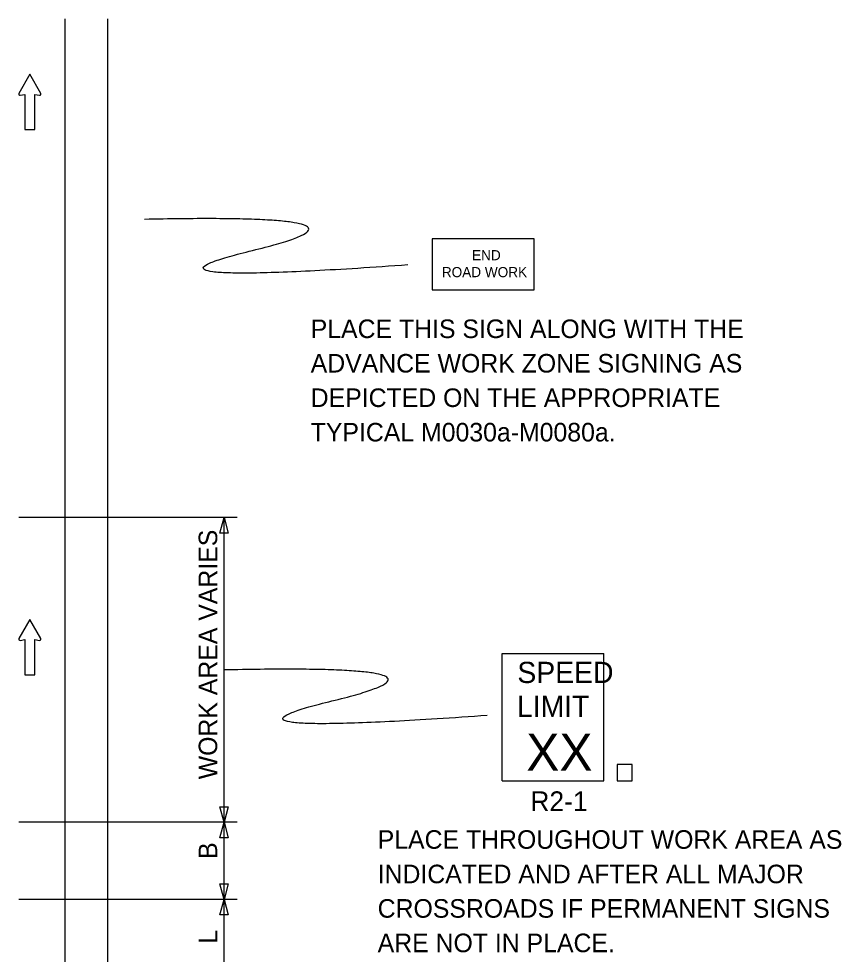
# Model space of a CAD drawing. Extents: x 16735 to 19504, y 6970 to 8243.
# Drawn here: x 18071.7 to 18381.9, y 7838.5 to 8191.4 of the extents above; entities that cross this region are included whole.
import ezdxf

# ---------------------------------------------------------------- set-up
doc = ezdxf.new("R2010")
doc.units = 0
for name, color, linetype in [('MT_SCRATCH_LEVEL_E', 7, 'Continuous'), ('PAVT_EDGE_EX', 7, 'Continuous'), ('TRAFFIC_SIGNS_PR', 7, 'Continuous'), ('TYPICAL_TEXT_DIMEN_PR', 7, 'Continuous')]:
    doc.layers.add(name, color=color, linetype=linetype)

msp = doc.modelspace()

# ---------------------------------------------------------------- linework, layer by layer
at = {"layer": 'MT_SCRATCH_LEVEL_E'}
for p, q in [((18075.82, 8170.46), (18071.71, 8163.22)), ((18075.82, 8170.46), (18071.71, 8163.22)), ((18079.97, 8163.22), (18075.82, 8170.46)), ((18079.97, 8163.22), (18075.82, 8170.46)), ((18072.19, 8162.54), (18073.97, 8162.86)), ((18072.19, 8162.54), (18073.97, 8162.86)), ((18073.97, 8162.86), (18073.97, 8149.6)), ((18073.97, 8162.86), (18073.97, 8149.6)), ((18077.71, 8149.6), (18077.71, 8162.86)), ((18077.71, 8162.86), (18079.49, 8162.54)), ((18077.71, 8149.6), (18077.71, 8162.86)), ((18077.71, 8162.86), (18079.49, 8162.54)), ((18073.97, 8149.6), (18077.71, 8149.6)), ((18073.97, 8149.6), (18077.71, 8149.6)), ((18075.82, 7964.84), (18071.71, 7957.6)), ((18075.82, 7964.84), (18071.71, 7957.6)), ((18079.97, 7957.6), (18075.82, 7964.84)), ((18079.97, 7957.6), (18075.82, 7964.84)), ((18072.19, 7956.91), (18073.97, 7957.23)), ((18072.19, 7956.91), (18073.97, 7957.23)), ((18073.97, 7957.23), (18073.97, 7943.97)), ((18073.97, 7957.23), (18073.97, 7943.97)), ((18077.71, 7943.97), (18077.71, 7957.23)), ((18077.71, 7957.23), (18079.49, 7956.91)), ((18077.71, 7943.97), (18077.71, 7957.23)), ((18077.71, 7957.23), (18079.49, 7956.91)), ((18073.97, 7943.97), (18077.71, 7943.97)), ((18073.97, 7943.97), (18077.71, 7943.97))]:
    msp.add_line(p, q, dxfattribs=at)
for centre, start, end in [((18072.12, 8163), 150.4248, 279.9638), ((18072.12, 8163), 150.4248, 279.9638), ((18079.56, 8163), 260.0362, 29.7731), ((18079.56, 8163), 260.0362, 29.7731), ((18072.12, 7957.37), 150.4248, 279.9638), ((18072.12, 7957.37), 150.4248, 279.9638), ((18079.56, 7957.37), 260.0362, 29.7731), ((18079.56, 7957.37), 260.0362, 29.7731)]:
    msp.add_arc(centre, 0.463, start, end, dxfattribs=at)
at = {"layer": 'PAVT_EDGE_EX'}
for p, q in [((18089.08, 8191.4), (18089.08, 7362.22)), ((18105.08, 8191.4), (18105.08, 7362.22))]:
    msp.add_line(p, q, dxfattribs=at)
at = {"layer": 'TRAFFIC_SIGNS_PR'}
for p, q in [((18253.94, 7951.98), (18292.34, 7951.98)), ((18253.94, 7903.98), (18253.94, 7951.98)), ((18292.34, 7903.98), (18292.34, 7951.98)), ((18253.94, 7903.98), (18292.34, 7903.98))]:
    msp.add_line(p, q, dxfattribs=at)
for points in [[(18227.62, 8089.16), (18266.02, 8089.16), (18266.02, 8108.36), (18227.62, 8108.36)], [(18297.36, 7903.98), (18302.95, 7903.98), (18302.95, 7910.15), (18297.36, 7910.15)]]:
    msp.add_lwpolyline(points, close=True, dxfattribs=at)
for points in [[(18218.38, 8098.52), (18103.15, 8090.28), (18217.06, 8117.86), (18119.12, 8115.7)], [(18248.34, 7928.58), (18133.11, 7920.34), (18247.02, 7947.93), (18149.08, 7945.76)]]:
    msp.add_open_spline(points, degree=2, dxfattribs=at)
at = {"layer": 'TYPICAL_TEXT_DIMEN_PR'}
for p, q in [((18154.08, 8003.21), (18071.68, 8003.21)), ((18147.51, 7997.35), (18149.08, 8003.21)), ((18149.08, 7888.3), (18149.08, 8003.21)), ((18149.08, 8003.21), (18150.65, 7997.35)), ((18149.08, 7997.35), (18147.51, 7997.35)), ((18150.65, 7997.35), (18149.08, 7997.35)), ((18149.08, 7888.3), (18147.51, 7894.16)), ((18147.51, 7894.16), (18149.08, 7894.16)), ((18149.08, 7894.16), (18150.65, 7894.16)), ((18150.65, 7894.16), (18149.08, 7888.3)), ((18154.08, 7888.3), (18071.68, 7888.3)), ((18147.51, 7882.44), (18149.08, 7888.3)), ((18149.08, 7859.25), (18149.08, 7888.3)), ((18149.08, 7888.3), (18150.65, 7882.44)), ((18149.08, 7882.44), (18147.51, 7882.44)), ((18150.65, 7882.44), (18149.08, 7882.44)), ((18149.08, 7859.25), (18147.51, 7865.11)), ((18147.51, 7865.11), (18149.08, 7865.11)), ((18149.08, 7865.11), (18150.65, 7865.11)), ((18150.65, 7865.11), (18149.08, 7859.25)), ((18154.08, 7859.25), (18071.68, 7859.25)), ((18147.51, 7853.39), (18149.08, 7859.25)), ((18149.08, 7828.68), (18149.08, 7859.25)), ((18149.08, 7859.25), (18150.65, 7853.39)), ((18149.08, 7853.39), (18147.51, 7853.39)), ((18150.65, 7853.39), (18149.08, 7853.39))]:
    msp.add_line(p, q, dxfattribs=at)

# ---------------------------------------------------------------- texts
at = {"layer": 'TRAFFIC_SIGNS_PR'}
for s, height, p in [('END', 3.831, (18242.62, 8100.29)), ('ROAD WORK', 3.831, (18231.23, 8093.91)), ('PLACE THIS SIGN ALONG WITH THE', 7, (18181.77, 8070.95)), ('ADVANCE WORK ZONE SIGNING AS', 7, (18181.77, 8057.95)), ('DEPICTED ON THE APPROPRIATE', 7, (18181.77, 8044.95)), ('TYPICAL M0030a-M0080a.', 7, (18181.77, 8031.95)), ('SPEED', 8, (18259.71, 7940.84)), ('LIMIT', 8, (18259.55, 7928.04)), ('XX', 14.031, (18263.05, 7907.74)), ('R2-1', 7.44, (18264.62, 7892.54)), ('PLACE THROUGHOUT WORK AREA AS', 7, (18207.03, 7878.32)), ('INDICATED AND AFTER ALL MAJOR', 7, (18207.03, 7865.32)), ('CROSSROADS IF PERMANENT SIGNS', 7, (18207.03, 7852.32)), ('ARE NOT IN PLACE.', 7, (18207.03, 7839.32))]:
    msp.add_text(s, height=height, dxfattribs=at).set_placement(p)
at = {"layer": 'TYPICAL_TEXT_DIMEN_PR'}
for s, p in [('WORK AREA VARIES', (18146.52, 7904.53)), ('B', (18146.52, 7874.51)), ('L', (18146.52, 7842.54))]:
    msp.add_text(s, height=7, rotation=90, dxfattribs=at).set_placement(p)

doc.saveas('drawing.dxf')
